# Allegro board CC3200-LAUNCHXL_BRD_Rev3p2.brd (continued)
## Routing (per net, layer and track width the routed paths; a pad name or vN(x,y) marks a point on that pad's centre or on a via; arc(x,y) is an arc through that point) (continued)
CC_GPIO_26: length 88.6
  TOP w0.152: U13.29 28.79,29.43 28.5,29.14 27.87,29.14 v1(27.81,29.08) ; v1(42.29,47.62) 43.81,47.62 44.83,46.61 44.83,45.21 45.59,44.45 R66.1 46.26,43.69 46.51,43.43 v1(47.24,43.43)
  BOTTOM w0.152: v1(27.81,29.08) 27.79,29.06 27.79,28.42 28.08,28.12 28.55,28.12 30.62,30.19 31.5,31.07 31.5,31.75 32.41,32.66 35.28,32.66 37.06,30.89 37.35,30.89 46.39,30.89 47.19,31.69 47.19,43.38 v1(47.24,43.43) ; J5.3 3.94,54.86 3.94,54.23 10.92,47.24 18.29,47.24 19.02,47.98 41.94,47.98 v1(42.29,47.62)
CC_GPIO_27: length 88.5
  TOP w0.152: R68.1 v1(45.47,41.91) ; U13.30 29.28,30.04 29.28,29.28 28.63,28.63 v1(28.29,28.63)
  PWR w0.152: v1(45.21,47.12) 45.97,46.35 45.97,42.42 v1(45.47,41.91) 44.7,41.15 44.7,39.19 46.1,37.79 46.1,32.28 45.21,31.39 v1(44.58,31.39)
  BOTTOM w0.152: v1(44.58,31.39) 44.42,31.24 37.21,31.24 35.43,33.02 32.26,33.02 31.14,31.9 31.14,31.21 30.89,30.96 28.56,28.63 v1(28.29,28.63) ; v1(45.21,47.12) 44.2,48.13 42.59,48.13 42.08,48.64 10.39,48.64 4.57,54.46 4.57,56.9 3.17,58.29 J5.4
CC_GPIO_28: length 54.5
  TOP w0.152: U13.18 23.29,29.52 23.06,29.28 22.28,29.28 v1(22.1,29.46) ; R69.2 55.34,42.57 54.99,42.93 44.32,42.93 v1(44.07,43.18) ; v1(45.47,32.64) 45.97,32.64 46.26,32.36 R88.1
  PWR w0.152: v1(44.07,43.18) 43.56,42.67 43.56,34.54 v1(45.47,32.64)
  BOTTOM w0.152: v1(22.1,29.46) 22.58,29.95 28.87,29.95 30.43,31.51 30.43,32.21 33.6,35.38 35.48,35.38 38.23,32.64 v1(45.47,32.64)
CC_GPIO_30: length 26.2
  TOP w0.152: U13.53 28.29,40.45 v1(28.35,40.51) ; R99.2 v1(14.48,25.65)
  PWR w0.152: v1(14.48,25.65) 16.26,25.65 22.1,31.5 22.1,38.1 23.5,39.5 27.34,39.5 v1(28.35,40.51)
CC_GPIO_31: length 21.1
  TOP w0.152: R80.2 55.34,37.37 54.74,37.97 48.64,37.97 48.01,38.61 44.42,38.61 42.11,40.92 42.11,44.76 41.43,45.44 R65.2
CC_NRESET: length 109.1
  TOP w0.152: U13.32 30.29,29.4 31.75,27.94 31.75,26.82 C46.1 32.4,25.03 R100.1 32.41,23.78 v1(32.54,23.65) ; v1(42.67,48.77) 43.18,49.28 56.52,49.28 57.28,50.04 57.28,75.06 53.98,78.36 47.37,78.36 46.29,79.44 D3.2 46.29,82.01 R5.2 46.26,82.45 46.48,82.68 46.99,82.68 47.22,82.9 R129.2 49.7,83.44 SW1.2 50.08,88.99 48.65,90.41 Q1.1
  PWR w0.152: v1(32.54,23.65) 32.58,23.69 37.78,23.69 42.82,28.73 42.82,48.62 v1(42.67,48.77)
DBG_RST_N: length 15.7
  TOP w0.152: U5.19 14.96,73.41 R30.2 14.07,72.13 13.83,71.89 12.05,71.89 v1(11.43,72.52) ; U9.10 11.48,65.01 12.45,65.98 v1(12.45,66.17)
  BOTTOM w0.152: v1(12.45,66.17) 12.19,66.42 12.19,71.75 v1(11.43,72.52)
DBGENN: length 25.7
  TOP w0.152: 6.42,79.76 6.81,79.36 8,79.36 8.26,79.11 ; 6.42,79.76 U4.4 ; 6.42,79.76 7.72,81.06 ; 7.72,81.06 6.77,82 ; 7.72,81.06 U4.13 ; 6.77,82 6.47,81.71 U4.1 ; 6.77,82 R4.2 ; 8.26,79.11 8.24,79.11 8,78.87 8,77.22 8.51,76.71 11.18,76.71 11.53,76.36 R22.2 11.53,74.45 12.45,73.53 R28.2 ; 8.26,79.11 U4.10
DBGMOD: length 16
  TOP w0.152: U4.5 5.86,79.11 v1(6.1,78.87) ; U4.2 v1(5.3,81.06) ; v1(10.79,77.22) 11.68,77.22 12.12,76.78 12.12,75.01 12.45,74.68 R26.2
  BOTTOM w0.152: v1(5.3,81.06) 6.1,80.26 v1(6.1,78.87) 7.75,77.22 v1(10.79,77.22)
FL_SWN: length 8.4
  TOP w0.254: U13.46 31.7,37.29 32.38,37.98 32.38,38.71
  TOP w0.381: L4.1 35.51,42.62 35.49,42.62 34.59,41.72 34.59,41.16 32.38,38.95 32.38,38.71
FL_SWP: length 13.9
  TOP w0.203: R65.1 39.09,43.18 L4.2
  TOP w0.254: 33.05,38.76 32.91,38.62 32.91,37.84 31.86,36.79 U13.45
  TOP w0.381: L4.2 38.12,43.16 38.12,42.31 37.85,42.04 35.73,42.04 35.18,41.48 35.18,40.89 33.05,38.76
FT_CS: length 15
  TOP w0.152: R34.2 11.72,71.25 v1(11.58,71.39) ; v1(6.1,68.2) 6.1,65.66 5.45,65.01 U9.5 ; U7.9 10.95,70.58 11.18,70.36 v1(11.18,70.23)
  BOTTOM w0.152: v1(6.1,68.2) 9.14,68.2 v1(11.18,70.23) 11.58,70.63 v1(11.58,71.39)
FT_DI: length 13.5
  TOP w0.152: U9.11 8.38,65.66 7.49,66.55 7.49,70.87 8.51,71.88 U7.11 10.79,71.88 11.05,71.63 11.05,71.2 12.02,70.23 R36.2
FT_DO: length 27.5
  TOP w0.152: v1(11.05,78.74) 10.77,78.46 U4.9 ; U7.2 2.95,73.18 2.79,73.33 2.79,74.55 6.73,78.49 v1(7.37,78.49) ; R41.2 13.46,68.07 v1(13.34,67.94)
  BOTTOM w0.152: v1(13.34,67.94) 14.1,68.71 14.1,73.98 11.68,76.39 11.68,78.11 v1(11.05,78.74) 7.62,78.74 v1(7.37,78.49)
FT_SK: length 20.1
  TOP w0.152: U4.12 8.14,80.41 v1(8,80.26) ; R46.2 13.59,66.93 v1(13.46,67.06)
  BOTTOM w0.152: v1(8,80.26) 10.24,80.26 12.04,78.47 12.04,76.54 14.45,74.13 14.45,68.05 v1(13.46,67.06)
FTDI_RX: length 6.9
  TOP w0.152: R53.2 26.54,67.69 27.53,68.68 R40.2
FTDI_TX: length 12.9
  TOP w0.152: R35.2 27.94,70.61 28.19,70.36 28.19,67.82 v1(27.81,67.44) ; U11.4 v1(21.67,62.06)
  BOTTOM w0.152: v1(27.81,67.44) 22.44,62.06 v1(21.67,62.06)
LP_GPIO_01: length 53.4
  TOP w0.152: v1(42.14,49.33) 42.14,48.54 42.42,48.26 53.21,48.26 57.53,43.94 57.53,25.65 56.01,24.13 R105.2
  BOTTOM w0.152: J7.1 32.51,50.67 33.78,49.4 42.06,49.4 v1(42.14,49.33)
LP_GPIO_02: length 20.4
  TOP w0.152: R70.2 v1(14.48,41.4)
  PWR w0.152: v1(14.48,41.4) 15.37,42.29 15.37,46.86 18.41,49.91 18.41,51.05 19.18,51.82 24.77,51.82 J6.1
LP_GPIO_25: length 39.4
  TOP w0.152: R98.2 56.01,26.67 57.02,27.69 57.02,34.54 56.01,35.56 48.77,35.56 48.26,35.05 46.48,35.05 46.26,34.83 R83.1 45.72,34.29 v1(45.47,34.54)
  PWR w0.152: v1(45.47,34.54) 44.89,35.12 44.89,38.5 44.35,39.04 44.35,42.74 44.7,43.1 44.7,48.9 J14.1
LP_RESET_OUT: length 54.5
  TOP w0.152: D3.1 52.42,80.68 v1(53.09,80.01) ; R84.2 v1(56.13,34.29)
  BOTTOM w0.152: v1(56.13,34.29) 57.28,35.43 57.28,75.82 v1(53.09,80.01)
PA_SWN: length 10.5
  TOP w0.254: U13.41 32.44,34.79 33.69,36.04 35.61,36.04 36.58,37.02 37.59,37.02
  TOP w0.505: 37.59,37.02 38.98,37.02 39.15,36.84 L6.1
PA_SWP: length 6.5
  TOP w0.254: 34.64,35.43 33.73,35.43 32.59,34.29 U13.40
  TOP w0.505: L6.2 34.64,35.43
SENS_I2C_SCL: length 12.8
  TOP w0.152: J3.1 47.75,66.93 48.13,66.55 R47.2
  TOP w0.203: R48.1 R47.2 50.07,67.85 50.67,68.45 52.45,68.45 53.03,69.03 R39.1
SENS_I2C_SDA: length 22.2
  TOP w0.152: R55.1 50.94,62.74 R54.2 49.76,63.22 49.6,63.37 48.9,63.37 46.61,65.66 43.22,65.66 42.8,66.08 42.8,68.45 J2.1 46.86,69.47 47.5,68.83 50.55,68.83 51.14,69.43 R38.1
SFL_CLK: length 14.5
  TOP w0.152: 17.02,33.15 18.07,32.11 19.96,32.11 21.15,33.29 U13.11 ; 17.02,33.15 17.4,33.53 17.4,37.06 17.25,37.21 15.65,37.21 15.49,37.06 U15.6 ; 17.02,33.15 U14.6
SFL_CS: length 17.2
  TOP w0.152: 12.95,30.96 12.95,29.59 13.59,28.96 13.92,28.96 14.17,28.7 16.89,28.7 19.2,31.01 20.38,31.01 21.16,31.79 U13.14
  TOP w0.203: 12.95,30.96 12.95,32.13 12.6,32.49 12.35,32.49 12.04,32.8 12.04,34 12.35,34.32 12.79,34.32 12.96,34.15 13.4,34.15
SFL_DIN: length 17.4
  TOP w0.152: 13.89,29.49 14.32,29.06 16.74,29.06 19.05,31.37 20.23,31.37 21.16,32.29 U13.13
  TOP w0.203: v1(13.86,29.49) 13.97,29.49 14.22,29.74 14.22,30.96 ; v1(12.57,33.78) 12.7,33.65 13.4,33.65
  BOTTOM w0.152: v1(13.86,29.49) 13.76,29.59 13.72,29.59 12.19,31.11 12.19,33.4 v1(12.57,33.78)
SFL_DOUT: length 10.6
  TOP w0.152: U15.5 16.76,34.52 v1(16.81,34.48) ; U14.5 16.5,32.65 v1(16.64,32.51) 16.99,32.51 17.75,31.75 20.11,31.75 21.15,32.79 U13.12
  BOTTOM w0.152: v1(16.64,32.51) 17.02,32.89 17.02,34.27 v1(16.81,34.48)
SOP0: length 49.1
  TOP w0.152: v1(32.14,31.64) 32.03,31.75 32,31.75 31.96,31.79 U13.35 ; J17.1 56.52,51.82 R59.1
  BOTTOM w0.152: J17.1 54.1,51.94 52.07,51.94 51.56,51.44 51.56,49.78 47.98,46.2 47.98,31.97 46.75,30.74 46.54,30.53 37.5,30.53 35.76,30.53 35.08,31.22 32.56,31.22 v1(32.14,31.64)
SOP1: length 44.8
  TOP w0.152: J16.1 54.1,51.94 54.1,55.65 R58.1 ; v1(32.13,30.86) 31.7,31.29 U13.34
  BOTTOM w0.152: v1(32.13,30.86) 34.93,30.86 35.62,30.18 37.65,30.18 46.69,30.18 47.1,30.59 48.41,31.9 48.41,45.36 52.83,49.78 J16.1
SOP2: length 6.7
  TOP w0.152: R60.1 R61.1 49.02,51.94 J15.1
SRSTN: length 50
  TOP w0.152: R129.1 45.72,83.44 45.34,83.06 45.34,79.12 44.45,78.23 39.5,78.23 32.38,71.12 32.38,65.91 27.43,60.96 20.89,60.96 20.56,60.63 19.71,60.63 19.05,61.29 19.05,61.85 17.78,63.12 R52.2
N24159: length 6.6
  TOP w0.203: 34.92,33.27 32.88,33.27 32.86,33.29 U13.38
  TOP w0.505: L7.2 35.98,32.6 35.31,33.27 34.92,33.27
N24403: length 8.6
  TOP w0.254: U13.43 32.15,35.79 33.31,36.96 35.05,36.96 35.38,37.29
  TOP w0.505: 35.38,37.29 35.43,37.34 35.43,38.73 36.49,39.79 L5.2
N27756: length 5.2
  TOP w0.254: 29.79,29.26 U13.31
  TOP w0.305: FL1.1 29.79,25.2
  TOP w0.457: 29.79,25.2 29.79,29.26
N28553: length 7.2
  TOP w0.152: C25.1 29.43,44.94 Y2.1 29.31,44.58 29.31,39.06 U13.51
N28565: length 8.8
  TOP w0.152: C26.1 26.58,44.81 Y2.2 26.69,43.68 26.84,43.53 27.91,43.53 28.96,42.48 28.96,40.26 28.79,40.1 U13.52
N30169: length 6.5
  TOP w0.152: U13.22 25.29,28.99 24.76,28.45 24,28.45 23.11,27.56 23.11,27.15 Y3.3 22.08,26.76 C47.1
N36298: length 41.3
  TOP w0.152: v1(11.43,26.29) 16.64,26.29 18.06,27.71 22.49,27.71 24.29,29.51 U13.20
  PWR w0.152: v1(11.43,26.29) 11.94,26.8 11.94,28.15 10.92,29.17 10.92,42.67 11.43,43.18 11.43,47.5 J9.2
N36324: length 37.9
  TOP w0.152: v1(11.43,27.94) 11.81,27.56 14.65,27.56 14.9,27.3 17.15,27.3 17.91,28.07 22.35,28.07 23.79,29.51 U13.19
  PWR w0.152: v1(11.43,27.94) 10.41,28.96 10.41,42.8 11.05,43.43 11.05,49.66 J8.2
N49988: length 7.6
  TOP w0.505: R57.2 J16.2 J15.2
  BOTTOM w0.505: J17.2 J16.2
N54209: length 2.1
  TOP w0.152: J22.3 R67.2
N54213: length 2.1
  TOP w0.152: J22.19 R106.2
N54217: length 2.1
  TOP w0.152: J22.5 R73.2
N54221: length 2.1
  TOP w0.152: J22.7 R78.2
N54244: length 2.1
  TOP w0.152: J22.15 R96.2
N54248: length 2.1
  TOP w0.152: J22.17 R102.2
N141545: length 3.3
  TOP w0.152: C48.1 23.98,25.02 Y3.1 24.92,24.16 R101.2
N178690: length 52.2
  TOP w0.152: R60.2 47.85,56.64 46.99,56.64 46.48,56.13 J14.2 ; U13.21 24.79,29.2 v1(24.54,28.96)
  BOTTOM w0.152: v1(24.54,28.96) 25.18,29.59 29.02,29.59 30.78,31.36 30.78,32.04 32.12,33.38 35.58,33.38 35.78,33.17 36.82,32.13 46.1,32.13 46.74,32.77 46.74,48.51 47.62,49.4 47.62,52.07 J14.2
N185612: length 9.7
  TOP w0.203: R42.1 R43.1 53.96,67.22 U10.7 54.3,65.71 54.72,65.3 C17.1 55.63,63.75 54.72,62.85 C21.1 53.46,62.98 U10.3
N185801: length 3
  TOP w0.203: U6.A3 53.98,72.27 54.24,72.53 C11.1 R27.1
N186121: length 1.5
  TOP w0.203: U10.1 51.1,64.08 R51.2
N186159: length 2.4
  TOP w0.203: R42.2 51.98,67.3 51.98,65.41 52.24,65.15 U10.11
N186206: length 1.6
  TOP w0.203: U10.12 51.66,64.65 R48.2
N186210: length 2.1
  TOP w0.152: U10.2 52.96,63.25 52.44,62.73 R55.2
N187169: length 3.2
  TOP w0.152: R31.2 R32.1
  TOP w0.203: U6.C1 50.7,73.27 R32.1
N187173: length 3
  TOP w0.203: U6.B1 R23.2 R24.1
N187525: length 2
  TOP w0.203: U6.B3 52.7,70.71 R39.2
N187543: length 2
  TOP w0.203: R38.2 52.21,70.71 U6.C3
N187584: length 4.2
  TOP w0.203: R37.1 50.24,70.23 50.67,70.23 51.31,70.87 51.31,72.3 51.78,72.77 U6.C2
N187626: length 15.5
  TOP w0.152: U10.5 54.73,64.65 v1(54.86,64.52)
  BOTTOM w0.152: v1(54.86,64.52) 53.72,65.66 42.55,65.66 J4.2
N192685: length 2.1
  TOP w0.152: J22.11 R87.2
N195183: length 1.7
  TOP w0.505: R20.2 31.99,78.44 D4.1
N195451: length 3.8
  TOP w0.152: U3.5 37,79.25 C6.2 35.66,79.24 R17.1 R18.2
N197053: length 5.4
  TOP w0.152: U13.23 25.79,28.95 25.02,28.18 25.02,25.5 R101.1
N224301: length 1.2
  TOP w0.457: R110.2 C49.1
N224305: length 5.2
  TOP w0.457: C49.2 33.71,20.01 arc(34.77,19.79) L8.2 36.61,18.25 36.62,18.25 J18.1
N224377: length 4.2
  TOP w0.305: FL1.3 29.79,23.8
  TOP w0.457: 29.79,23.8 R111.1
N224405: length 4.1
  TOP w0.457: R111.2 J24.1
N233208: length 3.8
  TOP w0.152: R103.1 J22.18
N288081: length 2.3
  TOP w0.152: J23.16 R98.1
N288085: length 3.6
  TOP w0.152: J23.14 R93.1 R90.1
N288162: length 2.3
  TOP w0.152: J23.4 R69.1
N288174: length 2.3
  TOP w0.152: J23.10 R84.1
N288178: length 3.6
  TOP w0.152: J23.12 R89.1 R86.1
N288672: length 3.5
  TOP w0.152: J23.3 R68.2 R71.2
N288674: length 2.3
  TOP w0.152: J23.5 R74.2
N288676: length 4.3
  TOP w0.152: R77.2 R79.2 ; R79.2 R81.2 ; R79.2 J23.7
N288678: length 3.3
  TOP w0.152: R85.2 R83.2 J23.9
N288680: length 2.3
  TOP w0.152: R88.2 J23.11
N288682: length 2.3
  TOP w0.152: J23.13 R92.2
N288684: length 2.3
  TOP w0.152: R97.2 J23.15
N288686: length 2.3
  TOP w0.152: J23.17 R104.2
N288688: length 2.3
  TOP w0.152: J23.19 R108.2
N288796: length 3.3
  TOP w0.152: R63.2 R66.2 J23.1
N292143: length 5.6
  TOP w0.762: J20.1 53.09,11.43 54.23,12.58 Q2.3 54.22,12.72 R112.1
N314690: length 5.5
  TOP w0.152: R56.1 22.38,55.75 J6.3
N329065: length 1.2
  TOP w0.505: R115.2 56.24,10.53 Q2.1
N394921: length 1.6
  TOP w0.505: U8.5 41.88,73.03 42.16,73.03 42.37,73.23 L3.2
N412421: length 4.7
  TOP w0.152: R70.1 10.92,41.4 J22.6
N412425: length 5.2
  TOP w0.152: J22.8 12.19,40.13 R72.1
N439074: length 2.3
  TOP w0.152: J23.20 R109.1
N439968: length 3.8
  TOP w0.152: R107.1 J22.20
N454667: length 2.3
  TOP w0.152: R80.1 J23.8
N454954: length 6.6
  TOP w0.152: J22.10 10.79,36.2 10.79,37.59 12.06,38.86 R76.1
N454967: length 5.5
  TOP w0.152: J22.12 8.89,31.37 12.06,28.19 R94.1
N466203: length 2.1
  TOP w0.152: J22.9 R82.2
N466207: length 2.1
  TOP w0.152: J22.13 R91.2
N466247: length 4.8
  TOP w0.152: J22.14 11.18,26.92 R95.1
N466251: length 4.3
  TOP w0.152: J22.16 9.91,25.65 R99.1
N466300: length 2.3
  TOP w0.152: R75.1 J23.6
N466314: length 2.3
  TOP w0.152: R105.1 J23.18
N474715: length 5.1
  TOP w0.457: J24.2 L9.1
N487558: length 6.5
  TOP w0.254: v1(20.7,80.52) 20.48,80.29 R9.2 ; R10.1 v1(22.61,81.92) ; U5.7 19.82,79.42 20.07,79.67 20.07,79.76
  TOP w0.4: 20.07,79.76 R9.2
  BOTTOM w0.254: v1(20.7,80.52) 21.21,80.52 v1(22.61,81.92)
N487570: length 3
  TOP w0.254: U5.6 20.32,78.99 20.57,79.25
  TOP w0.505: 20.57,79.25 21.21,79.88 21.21,79.93 21.46,80.18 C5.1
N487672: length 4.1
  TOP w0.254: 25.73,75.61 25.53,75.41 U5.46
  TOP w0.505: R21.1 26.95,75.83 C8.1 25.94,75.82 25.73,75.61
N487804: length 3.4
  TOP w0.152: R10.2 21.31,78.99 21.09,78.99 20.82,78.72 U5.5
N487824: length 2
  TOP w0.152: U5.26 17.82,67.57 R44.2
N487832: length 2.7
  TOP w0.152: U5.10 18.32,79.22 17.78,79.76 R7.2
N487932: length 4
  TOP w0.152: R40.1 26.01,70.03 26.01,71.15 25.25,71.91 U5.39
N488104: length 3.5
  TOP w0.152: U5.40 25.38,72.41 26.57,71.22 R35.1
N488180: length 9.4
  TOP w0.152: U5.1 22.82,78.57 23.24,78.99 23.24,80.01 v1(23.75,80.52) ; U2.2 26.73,80.55 R14.2 27.21,80.49 v1(27.3,80.39)
  BOTTOM w0.152: v1(23.75,80.52) 27.18,80.52 v1(27.3,80.39)
N488188: length 7.2
  TOP w0.152: U2.1 26.08,81.17 R13.2 24.86,80.49 24.19,79.82 U5.48
N488454: length 4.3
  TOP w0.152: U5.24 15.94,67.66 R46.1
N488458: length 4.6
  TOP w0.152: R41.1 15.21,68.58 14.77,69.02 14.77,71.18 15,71.41 U5.23
N488478: length 3.7
  TOP w0.152: R6.2 30.2,80.39 R12.1 29.05,80.8 28.03,81.83 U2.4
N488614: length 10.4
  TOP w0.152: v1(22.61,79.38) 22.32,79.09 U5.2 ; v1(28.07,79.63) 28.1,79.66 R12.2 27.38,81.11 U2.3
  BOTTOM w0.152: v1(22.61,79.38) 27.81,79.38 v1(28.07,79.63)
N488706: length 7.2
  TOP w0.152: U5.44 24.2,74.42 25.53,74.42 26.27,73.68 C10.1 27.46,73.71 30.09,73.71 Y1.1
N488714: length 6.2
  TOP w0.152: Y1.2 27.83,73.03 C12.1 26.56,72.63 25.28,73.91 U5.43
N489641: length 3.5
  TOP w0.152: U5.22 14.96,71.91 14.39,71.34 14.39,70.39 14.22,70.23 R36.1
N489651: length 2.7
  TOP w0.152: U5.21 14.95,72.41 14.2,71.65 14.1,71.65 R34.1
N490588: length 1.2
  TOP w0.381: 11.43,88.77 11.15,89.05 J1.1
N490592: length 3.1
  TOP w0.381: 8.26,88.65 8.55,88.94 J1.5
  TOP w0.505: 8.26,88.65 7.94,88.33 L1.2
N490656: length 18.9
  TOP w0.4: v1(19.05,81.92) 18.92,81.79 R8.1 ; v1(10.41,85.17) 10.2,85.38 U1.2 10.67,86.74 10.67,88.13 10.5,88.31 J1.2
  BOTTOM w0.4: v1(10.41,85.17) 10.19,84.94 10.19,82.62 11.96,80.85 18.72,80.85 19.14,81.28 19.14,81.82 v1(19.05,81.92)
N490660: length 21.3
  TOP w0.4: v1(9.27,85.17) 9.5,85.4 U1.1 9.27,86.49 9.27,87.92 9.27,87.93 9.27,87.94 9.64,88.31 9.66,88.31 9.85,88.5 J1.3 ; R9.1 20.07,81.79 v1(19.94,81.92)
  BOTTOM w0.4: v1(19.94,81.92) 19.84,81.82 19.84,80.99 19.01,80.15 11.67,80.15 9.49,82.33 9.49,84.94 v1(9.27,85.17)
N497403: length 2.7
  TOP w0.254: 18.92,79.76 19.32,79.36 U5.8
  TOP w0.4: 18.92,79.76 R8.2
N507782: length 2.2
  TOP w0.152: R28.1 14.95,74.41 U5.17
N507786: length 2
  TOP w0.152: R26.1 14.3,74.91 U5.16
N508362: length 22
  TOP w0.152: v1(5.59,65.91) 5.33,65.66 U9.4 ; U4.6 2.16,78.46 R16.2 2.13,77.12 v1(3.17,76.07) ; U9.13 v1(8.51,66.96)
  BOTTOM w0.152: v1(3.17,76.07) 3.81,75.44 3.81,67.69 v1(5.59,65.91) 7.46,65.91 v1(8.51,66.96)
N508615: length 17
  TOP w0.152: U7.13 9.65,73.15 v1(8,73.15) ; U7.10 8.58,71.23 v1(8.3,70.95) ; v1(5.33,80.26) 5.19,80.41 U4.3 2.15,80.41 R11.1
  BOTTOM w0.152: v1(8.3,70.95) 8.3,72.86 v1(8,73.15) 5.33,75.82 v1(5.33,80.26)
N509670: length 1.9
  TOP w0.152: R15.1 U4.11
N509674: length 1.9
  TOP w0.152: U4.8 9.6,77.85 R19.1
N511498: length 14.9
  TOP w0.152: U7.1 5.03,73.83 6.73,72.14 6.73,65.66 5.43,64.36 2.29,64.36 R49.1
N512182: length 15.6
  TOP w0.152: U7.8 8.97,69.93 8.13,69.09 v1(8.13,68.96) 8,68.83 8,66.67 8.37,66.31 U9.12 ; v1(5.97,69.09) 6.22,69.34 6.22,71.95 5.64,72.53 U7.3 2.27,72.53 R29.1
  BOTTOM w0.152: v1(8.13,68.96) 8,69.09 v1(5.97,69.09)
N512199: length 5
  TOP w0.152: R25.1 6.83,73.56 7.86,72.53 U7.12
N517852: length 1.8
  TOP w0.152: R50.1 9.71,64.39 9.68,64.36
N517913: length 1.7
  TOP w0.152: D2.2 R4.1
N518669: length 2
  TOP w0.152: R52.1 10.87,63.71 U9.8
N519131: length 1.8
  TOP w0.152: U7.5 2.27,71.23 R33.1
N519138: length 1.8
  TOP w0.152: R45.1 2.29,66.96 U9.2
N532592: length 5.5
  TOP w0.152: U12.3 25.16,59.04 J7.3
N532639: length 1.4
  TOP w0.152: U12.4 25.22,62 R53.1
N533262: length 1.7
  TOP w0.152: U11.3 20.97,58.15 R56.2
N553084: length 5
  TOP w0.152: SW2.2 44.38,7.58 R124.2
N553120: length 2.6
  TOP w0.152: R116.2 SW3.2
N553666: length 5
  TOP w0.152: SW1.1 55.08,88 R1.2
N555301: length 1.5
  TOP w0.152: D1.2 44.01,87 R3.1
N555325: length 1.4
  TOP w0.152: Q1.3 47.03,88.37 R3.2
N555403: length 2.8
  TOP w0.254: R127.1 25.57,2.69 D7.2
N555427: length 2.8
  TOP w0.254: D5.2 14.8,5.44 R125.1
N555431: length 2.8
  TOP w0.254: R126.1 19.37,5.44 D6.2
N555483: length 2.1
  TOP w0.152: Q5.3 24.52,6.87 23.96,6.31 R127.2
N555487: length 1.7
  TOP w0.152: R126.2 20.99,6.2 Q4.3
N555495: length 1.7
  TOP w0.152: Q3.3 16.42,6.07 R125.2
N555589: length 1.1
  TOP w0.152: Q3.1 R119.2
N555601: length 1.1
  TOP w0.152: R121.2 Q4.1
N555605: length 1.1
  TOP w0.152: Q5.1 25.91,8.94 R123.2

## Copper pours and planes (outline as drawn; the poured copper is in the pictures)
GND on TOP: 0.51,91.31 2.67,93.47 56.26,93.47 57.91,91.82 57.91,89.28 57.85,89.22 57.85,87.31 57.91,87.25 57.91,8.13 57.91,3.17 57.85,3.11 57.85,1.97 56.39,0.51 3.3,0.51 0.51,3.3 ; 37 cut-outs
GND on BOTTOM: 0.51,91.31 2.67,93.47 54.48,93.47 57.91,90.04 57.91,8.13 57.91,3.17 55.24,0.51 3.68,0.51 0.51,3.68 ; 31 cut-outs
GND on GND: 0.51,91.31 2.67,93.47 54.48,93.47 57.91,90.04 57.91,8.13 57.91,3.17 57.85,3.11 57.85,1.97 56.39,0.51 3.68,0.51 0.51,3.68 ; 6 cut-outs
GND on PWR: 1.52,0.64 0.51,1.65 0.51,51.18 0.76,51.44 3.81,51.44 3.81,51.05 3.68,50.93 3.68,43.43 4.32,42.8 10.29,42.8 10.29,28.7 11.56,27.43 11.94,27.43 12.95,28.45 12.95,28.83 19.68,28.83 21.97,31.11 21.97,38.23 23.24,39.5 29.46,39.5 29.97,38.99 29.97,29.84 28.19,28.07 26.04,28.07 25.53,27.56 25.53,26.29 25.91,25.91 25.91,24.77 27.56,23.11 37.59,23.11 38.67,24.19 38.67,29.15 39.37,29.84 42.29,29.84 42.55,29.59 42.55,28.19 42.93,27.81 46.48,27.81 46.74,28.07 46.74,38.61 46.23,39.12 46.23,48.13 46.86,48.77 57.53,48.77 57.78,48.51 57.78,1.14 57.28,0.64 ; 3 cut-outs
VBAT_CC on TOP: 30.73,51.31 30.73,49.28 30.99,49.02 40.64,49.02 41.53,49.91 41.53,51.31 41.27,51.56 30.99,51.56
VBAT_CC on PWR: 19.18,51.56 17.91,50.29 17.91,42.29 14.48,38.86 14.48,30.48 14.99,29.97 14.99,29.46 15.37,29.08 18.8,29.08 21.84,32.13 21.84,38.73 23.24,40.13 30.23,40.13 32.13,42.04 33.02,42.04 33.66,41.4 33.66,40.39 33.02,39.75 33.02,31.75 33.53,31.24 35.31,31.24 35.56,31.5 35.56,51.05 35.05,51.56
VBUS_USB1 on TOP: 33.86,83.62 34.11,83.87 35.99,83.87 36.25,83.62 36.25,82.96 36.35,82.85 38.15,82.85 38.25,82.96 38.25,85.19 38.15,85.29 37.59,85.29 37.34,85.55 37.34,87.88 37.21,88.01 35.69,88.01 35.05,87.38 32,87.38 31.75,87.12 31.75,84.45 32.59,83.62
VBUS_USB1 on BOTTOM: 35.94,85.72 32.26,85.72 28.7,82.17 28.7,78.74 27.69,77.72 22.35,77.72 21.08,76.45 21.08,73.15 22.1,72.14 26.92,72.14 31.94,77.15 31.94,80.2 34.8,83.06 35.56,83.06 36.32,83.82 36.32,85.34
VCC_BRD on TOP: 30.99,53.98 30.99,52.32 35.18,52.32 35.43,52.58 35.43,53.98 35.05,54.36 31.37,54.36
VCC_BRD on PWR: 0.51,52.32 0.51,61.98 1.14,62.61 24,62.61 25.62,64.23 28.67,64.23 29.46,65.02 29.46,72.14 29.21,72.39 29.21,75.18 29.46,75.44 29.46,76.33 30.99,77.85 36.45,77.85 36.83,78.23 36.83,93.22 36.96,93.34 55.24,93.34 57.91,90.68 57.91,49.4 57.77,49.26 40.39,49.26 40.38,49.27 36.2,49.27 36.07,49.4 36.07,51.44 35.18,52.32 14.63,52.32 10.68,48.38 10.68,43.83 10.29,43.43 4.57,43.43 4.19,43.81 4.19,51.69 3.94,51.94 0.89,51.94
VCC_LDO_3V3 on PWR: 25.4,64.77 28.32,64.77 28.96,65.41 28.96,72.01 28.7,72.26 28.7,75.31 28.96,75.56 28.96,76.58 30.73,78.36 36.07,78.36 36.32,78.61 36.32,86.11 35.43,87 1.65,87 0.64,85.98 0.64,63.37 0.89,63.12 23.75,63.12
VDD_ANA on PWR: 38.1,27.94 37.85,28.19 36.32,28.19 34.8,26.67 33.02,26.67 32.77,26.92 32.77,29.46 33.27,29.97 33.27,30.73 32.51,31.5 32.51,40.01 33.15,40.64 33.15,41.15 32.77,41.53 32.38,41.53 30.48,39.62 30.48,29.72 28.32,27.56 26.29,27.56 26.16,27.43 26.16,26.42 26.42,26.16 26.42,25.02 27.81,23.62 36.45,23.62 38.1,25.27
VDD_PA on TOP: 34.42,29.59 33.27,29.59 33.15,29.46 33.15,27.69 33.4,27.43 34.16,27.43 34.54,27.81 34.54,29.46
VDD_PA on PWR: 42.55,48.39 42.16,48.77 36.2,48.77 36.07,48.64 36.07,31.11 35.69,30.73 33.91,30.73 33.78,30.61 33.78,29.72 33.27,29.21 33.27,27.43 33.53,27.18 34.54,27.18 36.32,28.96 37.72,28.96 39.24,30.48 41.91,30.48 42.55,31.11
N490588 on TOP: 11.2,86.33 12.22,86.33 12.37,86.49 12.37,88.42 11.51,89.28 11.51,90.5 11.43,90.58 10.95,90.58 10.87,90.5 10.87,89.03 11.07,88.82 11.07,86.46

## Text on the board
Ref Des/Silkscreen Bottom: VCC | P58 | P04 | P03 | P61 | P59 | P05 | P62 | P01 | P02 | 5V | P57 | P60 | GND | P63 | P53 | P50 | P64 | P17 | P29 | P16 | P30 | P07 | P06 | RST | P21 | P55 | P15 | P18 | P08 | P45 | P4 | P2 | P1 | P3 | Model: CC3200-LAUNCHXLA | FCC ID: Z64-CC3200KITA | IC ID: 451I-CC3200KITA
User.Comments: UNLESS OTHERWISE SPECIFIED | ALL DIMENSIONS ARE IN | INCHES | MILLIMETERS | REV C | JUNE 24 2014 | DATE | PART NUMBER: | CC3200LP 3.2 | A | FABRICATION DRAWING | TEXAS INSTRUMENTS | X
Ref Des/Silkscreen Top: P58 | P04 | P03 | P61 | P59 | P05 | P62 | P01 | P02 | DBGENn | GND | VCC | 5V | P4(GP13) | P30(G27) | P29(G26) | MAC | NWP | TCK | TMS | P63 | P60 | P53 | P57 | P50 | P64 | TDI | TDO | RX | TX | PWR | 3.3V | CC | FOR P21->BP | SHORT J14 | P15(GP22) | EMU | BRD | P29 | P30 | P17 | P21 | P18 | P16 | SDA | INT | SCL | 001:2W SWD | 000:4W JTAG | 100:FLASH | SOP | P08 | P45 | RST | P06 | P07 | P55 | P15 | P2(GP11) | FLASH | BP | P1(GP10) | P64(GP09) | P1 | P3 | Rev 3.2 | SENSORS | P4 | 2 | RESET | P2 | 1 | 0 | 2XAA | * | CC3200-LAUNCHXL | LAUNCHPAD
PAGE_OUTLINE: CAD | DATA | DO NOT MANUALLY | UPDATE | D | C | B | A | 8 | 7 | 6 | 5 | 4 | 3 | 2 | 1
DISPLAY_TOP: NOTES: UNLESS OTHERWISE SPECIFIED. | 9. MINIMUM CONDUCTOR WIDTH:4.0 MILS | REQUIREMENTS. | COPPER: AS PER STACKUP. | DIELECTRIC: FR4 | U.L. RATING: 94V-0 MINIMUM | 11.12MIL VIAS ARE TENTED IN BOTH THE MASK LAYER. | 1. FABRICATE PER IPC-6012A CLASS 2. | 2. SURFACE FINISH:  ENIG | 5. 100% CONTINUITY TESTING USING DATABASE NETLIST SHALL BE PERFORMED, | VENDOR TO IDENTIFY TEST PASSED IN SECONDARY  SIDE. | 3. SOLDER MASK MATERIAL SHALL MEET ALL THE REQUIREMENTS OF | IPC-SM-840C AND SHALL BE GREEN IN COLOR AND APPLIED OVER BARE COPPER. | 6. VENDOR TO MARK DATE CODE AND LOGO  IN ETCH OR IN LEGEND. | 10.SOLDER MASK CLEARANCE IS GIVEN SAME AS PAD SIZE EXCEPT NPTH AND FIDUCIALS. | 4. SILK SCREEN LEGEND TO BE APPLIED PER LAYER STACKUP USING WHITE | NON-CONDUCTIVE EPOXY INK. | 12.0.0121" VIAS ARE TO BE FILLED WITH NON-CONDUCTIVE EPOXY(VENDOR CHOICE) AND PLATED | 8. DIELECTRICS AND LINEWIDTHS MAY BE ADJUSTED TO MEET THE IMPEDANCE | 7. BOW AND TWIST SHALL NOT EXCEED 0.7% OF LONGEST SIDE . | VENDER SHALL MODIFY THE MASK CLEARANCE AS PER THE REQUIRED MANUFACTURING TOLERANCE. | +0.000"/-0.001" ON TOP SIDE AND +0.000"/-0.003" ON THE BOTTOM SIDE. | OVER WITH COPPER NICKEL AND GOLD. SURFACE MUST BE FLAT. FLATNESS TOLERANCE IS | MINIMUM SPACING:4.0 MILS
DIMENSION: ASSEMBLY PRIMARY SIDE
User.6: FABRICATION DRAWING | LAYER NO | 1 | CONDUCTOR WIDTH | 18.0 MIL | CONTROLLED IMPEDANCE USING CPW with GND | SPACING | 15 mil | IMPEDANCE +/- 10% | 50 OHMS | REFERENCE GND | L2
User.7: P2 | P4 | P3 | P1 | ASSEMBLY SECONDARY SIDE
User.8: 1.4 mm+/-10% | 4-LAYER STACK BUILD | SOLDER MASK(RED)------------->0.025 mm | SECONDARY SIDE, SILK SCREEN | LAYER 3                 ----->0.035 mm | DIELECTRIC              ----->0.255 mm | LAYER 4                 ----->0.035 mm | PRIMARY SIDE, SILK SCREEN | LAYER 1                 ----->0.035 mm | LAYER 2                 ----->0.035 mm | DIELECTRIC              ----->0.7   mm
User.14: DATE:JUNE 24 2014 | PART NO/CARD REF: | FILM LAYER: | CC3200LP 3.2 | DESIGNED BY: | COMPANY NAME : TEXAS INSTRUMENTS
User.15: LAYER 1 (TOP SIDE)
User.16: LAYER 2 (GND)
User.17: LAYER 3 (PWR)
User.20: LAYER 4(BOTTOM SIDE)
User.21: PRIMARY SIDE SILKSCREEN
User.22: SECONDARY SIDE  SILKSCREEN
User.23: PRIMARY SIDE PASTE LAYER
User.24: SECONDARY SIDE PASTE LAYER
User.25: PRIMARY SIDE SOLDERMASK
User.26: SECONDARY SIDE SOLDERMASK
User.27: OUTLINE
User.31: GENERAL NOTES-- UNLESS OTHERWISE SPECIFIED: | 1.   FABRICATE PER IPC-6012A CLASS 2 | 2.   SURFACE FINISH   :  ENIG | 3.   MATERIAL; FR4 | 5.   COPPER WT: 1 Oz | 6.   SOLDER MASK CLEARANCE IS GIVEN | 7. SOLDER MASK COLOUR : RED | SAME AS PAD SIZE EXCEPT FIDUCIAL | VENDOR SHALL MODIFY THE MASK CLEARANCE AS PER | THE REQUIRED MANUFACTURING TOLERANCE | SECTION A-A | NO SCALE
User.33: FIGURE | SIZE | 8.0 | 12.0 | 16.0 | 20.0 | 38.0 | 39.3701 | 98.4252 | 33.4646x21.6535 | 45.2756x19.685 | DRILL CHART: TOP to BOTTOM | ALL UNITS ARE IN MILS | TOLERANCE | +3.0/-3.0 | +2.0/-2.0 | PLATED | NON-PLATED | QTY | 433 | 158 | 20 | 2 | 83 | 6 | 4
